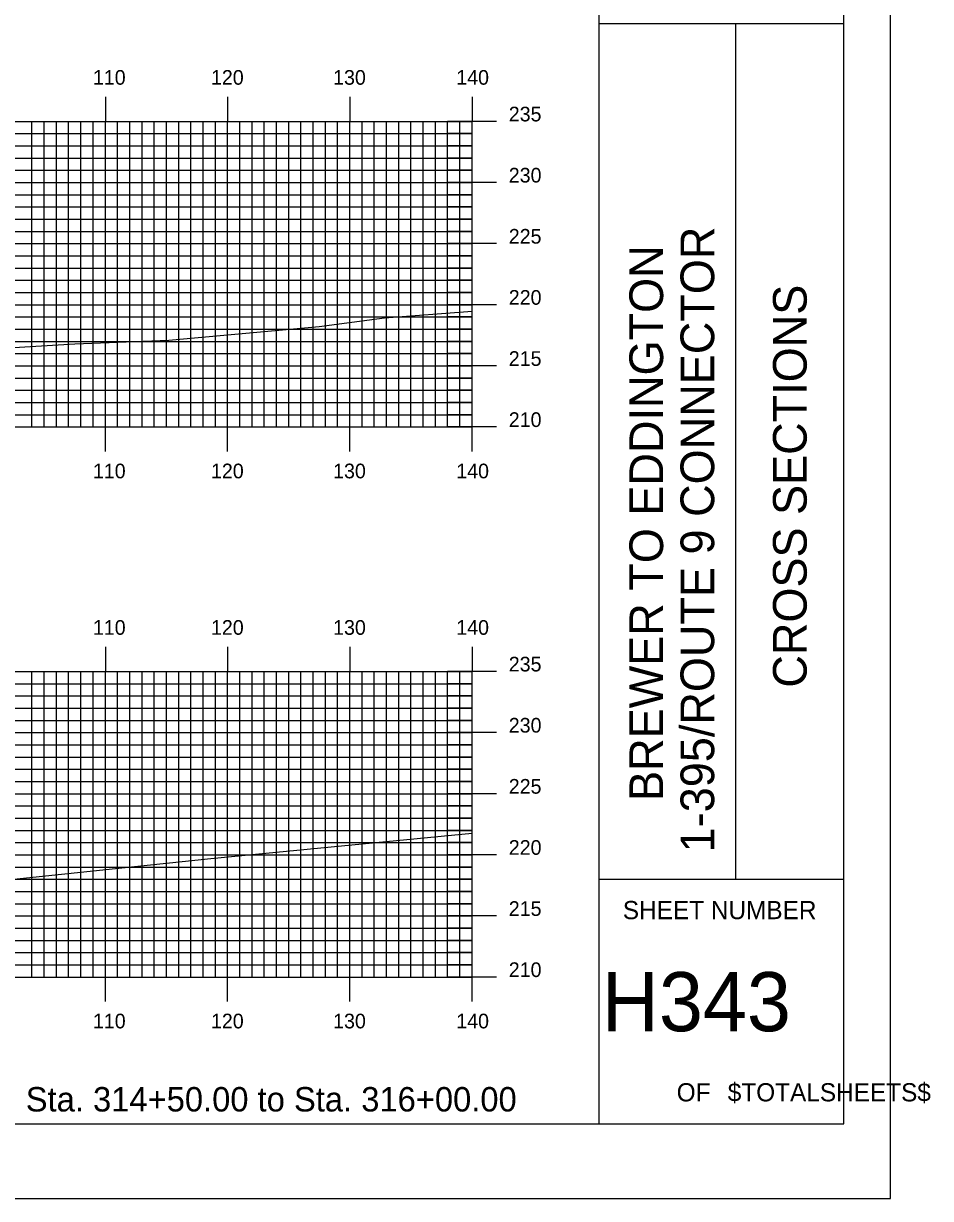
# Model space of a CAD drawing. Extents: x 1819244 to 1819587, y 442591 to 442811.
# Drawn here: x 1819513 to 1819587.2, y 442590.5 to 442686.7 of the extents above; entities that cross this region are included whole.
import ezdxf

# ---------------------------------------------------------------- set-up
doc = ezdxf.new("R2010")
doc.units = 0
for name, color, linetype in [('BORDER', 7, 'Continuous'), ('H_V ANNOTATION', 7, 'Continuous'), ('MAJOR', 7, 'Continuous'), ('MINOR', 7, 'Continuous'), ('PLOT BOUNDARY', 7, 'Continuous'), ('S_Roadway_Centerline', 7, 'Continuous')]:
    doc.layers.add(name, color=color, linetype=linetype)

msp = doc.modelspace()

# ---------------------------------------------------------------- linework, layer by layer
at = {"layer": 'BORDER'}
for p, q in [((1819560.065, 442596.665), (1819560.065, 442806.665)), ((1819560.065, 442686.671), (1819580.065, 442686.671)), ((1819571.247, 442616.671), (1819571.247, 442686.671)), ((1819560.065, 442616.671), (1819580.065, 442616.671))]:
    msp.add_line(p, q, dxfattribs=at)
msp.add_lwpolyline([(1819260.065, 442596.665), (1819580.065, 442596.665), (1819580.065, 442806.665), (1819260.065, 442806.665)], close=True, dxfattribs=at)
at = {"layer": 'MAJOR'}
for p, q in [((1819519.665, 442680.669), (1819519.665, 442678.665)), ((1819529.665, 442680.669), (1819529.665, 442678.665)), ((1819539.665, 442680.669), (1819539.665, 442678.665)), ((1819549.665, 442680.669), (1819549.665, 442678.665)), ((1819269.665, 442678.665), (1819549.665, 442678.665)), ((1819269.665, 442678.665), (1819549.665, 442678.665)), ((1819519.665, 442653.665), (1819519.665, 442678.665)), ((1819529.665, 442653.665), (1819529.665, 442678.665)), ((1819539.665, 442653.665), (1819539.665, 442678.665)), ((1819551.669, 442678.665), (1819547.661, 442678.665)), ((1819549.665, 442653.665), (1819549.665, 442678.665)), ((1819549.665, 442653.665), (1819549.665, 442678.665)), ((1819269.665, 442673.665), (1819549.665, 442673.665)), ((1819551.669, 442673.665), (1819547.661, 442673.665)), ((1819269.665, 442668.665), (1819549.665, 442668.665)), ((1819551.669, 442668.665), (1819547.661, 442668.665)), ((1819269.665, 442663.665), (1819549.665, 442663.665)), ((1819551.669, 442663.665), (1819547.661, 442663.665)), ((1819269.665, 442658.665), (1819549.665, 442658.665)), ((1819551.669, 442658.665), (1819547.661, 442658.665)), ((1819269.665, 442653.665), (1819549.665, 442653.665)), ((1819269.665, 442653.665), (1819549.665, 442653.665)), ((1819519.665, 442651.661), (1819519.665, 442653.665)), ((1819529.665, 442651.661), (1819529.665, 442653.665)), ((1819539.665, 442651.661), (1819539.665, 442653.665)), ((1819551.669, 442653.665), (1819547.661, 442653.665)), ((1819549.665, 442651.661), (1819549.665, 442653.665)), ((1819519.665, 442635.669), (1819519.665, 442633.665)), ((1819529.665, 442635.669), (1819529.665, 442633.665)), ((1819539.665, 442635.669), (1819539.665, 442633.665)), ((1819549.665, 442635.669), (1819549.665, 442633.665)), ((1819269.665, 442633.665), (1819549.665, 442633.665)), ((1819269.665, 442633.665), (1819549.665, 442633.665)), ((1819519.665, 442608.665), (1819519.665, 442633.665)), ((1819529.665, 442608.665), (1819529.665, 442633.665)), ((1819539.665, 442608.665), (1819539.665, 442633.665)), ((1819551.669, 442633.665), (1819547.661, 442633.665)), ((1819549.665, 442608.665), (1819549.665, 442633.665)), ((1819549.665, 442608.665), (1819549.665, 442633.665)), ((1819269.665, 442628.665), (1819549.665, 442628.665)), ((1819551.669, 442628.665), (1819547.661, 442628.665)), ((1819269.665, 442623.665), (1819549.665, 442623.665)), ((1819551.669, 442623.665), (1819547.661, 442623.665)), ((1819269.665, 442618.665), (1819549.665, 442618.665)), ((1819551.669, 442618.665), (1819547.661, 442618.665)), ((1819269.665, 442613.665), (1819549.665, 442613.665)), ((1819551.669, 442613.665), (1819547.661, 442613.665)), ((1819269.665, 442608.665), (1819549.665, 442608.665)), ((1819269.665, 442608.665), (1819549.665, 442608.665)), ((1819519.665, 442606.661), (1819519.665, 442608.665)), ((1819529.665, 442606.661), (1819529.665, 442608.665)), ((1819539.665, 442606.661), (1819539.665, 442608.665)), ((1819551.669, 442608.665), (1819547.661, 442608.665)), ((1819549.665, 442606.661), (1819549.665, 442608.665))]:
    msp.add_line(p, q, dxfattribs=at)
at = {"layer": 'MINOR'}
for p, q in [((1819513.665, 442653.665), (1819513.665, 442678.665)), ((1819514.665, 442653.665), (1819514.665, 442678.665)), ((1819515.665, 442653.665), (1819515.665, 442678.665)), ((1819516.665, 442653.665), (1819516.665, 442678.665)), ((1819517.665, 442653.665), (1819517.665, 442678.665)), ((1819518.665, 442653.665), (1819518.665, 442678.665)), ((1819520.665, 442653.665), (1819520.665, 442678.665)), ((1819521.665, 442653.665), (1819521.665, 442678.665)), ((1819522.665, 442653.665), (1819522.665, 442678.665)), ((1819523.665, 442653.665), (1819523.665, 442678.665)), ((1819524.665, 442653.665), (1819524.665, 442678.665)), ((1819525.665, 442653.665), (1819525.665, 442678.665)), ((1819526.665, 442653.665), (1819526.665, 442678.665)), ((1819527.665, 442653.665), (1819527.665, 442678.665)), ((1819528.665, 442653.665), (1819528.665, 442678.665)), ((1819530.665, 442653.665), (1819530.665, 442678.665)), ((1819531.665, 442653.665), (1819531.665, 442678.665)), ((1819532.665, 442653.665), (1819532.665, 442678.665)), ((1819533.665, 442653.665), (1819533.665, 442678.665)), ((1819534.665, 442653.665), (1819534.665, 442678.665)), ((1819535.665, 442653.665), (1819535.665, 442678.665)), ((1819536.665, 442653.665), (1819536.665, 442678.665)), ((1819537.665, 442653.665), (1819537.665, 442678.665)), ((1819538.665, 442653.665), (1819538.665, 442678.665)), ((1819540.665, 442653.665), (1819540.665, 442678.665)), ((1819541.665, 442653.665), (1819541.665, 442678.665)), ((1819542.665, 442653.665), (1819542.665, 442678.665)), ((1819543.665, 442653.665), (1819543.665, 442678.665)), ((1819544.665, 442653.665), (1819544.665, 442678.665)), ((1819545.665, 442653.665), (1819545.665, 442678.665)), ((1819546.665, 442653.665), (1819546.665, 442678.665)), ((1819547.665, 442653.665), (1819547.665, 442678.665)), ((1819548.665, 442653.665), (1819548.665, 442678.665)), ((1819269.665, 442677.665), (1819549.665, 442677.665)), ((1819549.665, 442677.665), (1819547.661, 442677.665)), ((1819269.665, 442676.665), (1819549.665, 442676.665)), ((1819549.665, 442676.665), (1819547.661, 442676.665)), ((1819269.665, 442675.665), (1819549.665, 442675.665)), ((1819549.665, 442675.665), (1819547.661, 442675.665)), ((1819269.665, 442674.665), (1819549.665, 442674.665)), ((1819549.665, 442674.665), (1819547.661, 442674.665)), ((1819269.665, 442672.665), (1819549.665, 442672.665)), ((1819549.665, 442672.665), (1819547.661, 442672.665)), ((1819269.665, 442671.665), (1819549.665, 442671.665)), ((1819549.665, 442671.665), (1819547.661, 442671.665)), ((1819269.665, 442670.665), (1819549.665, 442670.665)), ((1819549.665, 442670.665), (1819547.661, 442670.665)), ((1819269.665, 442669.665), (1819549.665, 442669.665)), ((1819549.665, 442669.665), (1819547.661, 442669.665)), ((1819269.665, 442667.665), (1819549.665, 442667.665)), ((1819549.665, 442667.665), (1819547.661, 442667.665)), ((1819269.665, 442666.665), (1819549.665, 442666.665)), ((1819549.665, 442666.665), (1819547.661, 442666.665)), ((1819269.665, 442665.665), (1819549.665, 442665.665)), ((1819549.665, 442665.665), (1819547.661, 442665.665)), ((1819269.665, 442664.665), (1819549.665, 442664.665)), ((1819549.665, 442664.665), (1819547.661, 442664.665)), ((1819269.665, 442662.665), (1819549.665, 442662.665)), ((1819549.665, 442662.665), (1819547.661, 442662.665)), ((1819269.665, 442661.665), (1819549.665, 442661.665)), ((1819549.665, 442661.665), (1819547.661, 442661.665)), ((1819269.665, 442660.665), (1819549.665, 442660.665)), ((1819549.665, 442660.665), (1819547.661, 442660.665)), ((1819269.665, 442659.665), (1819549.665, 442659.665)), ((1819549.665, 442659.665), (1819547.661, 442659.665)), ((1819269.665, 442657.665), (1819549.665, 442657.665)), ((1819549.665, 442657.665), (1819547.661, 442657.665)), ((1819269.665, 442656.665), (1819549.665, 442656.665)), ((1819549.665, 442656.665), (1819547.661, 442656.665)), ((1819269.665, 442655.665), (1819549.665, 442655.665)), ((1819549.665, 442655.665), (1819547.661, 442655.665)), ((1819269.665, 442654.665), (1819549.665, 442654.665)), ((1819549.665, 442654.665), (1819547.661, 442654.665)), ((1819513.665, 442608.665), (1819513.665, 442633.665)), ((1819514.665, 442608.665), (1819514.665, 442633.665)), ((1819515.665, 442608.665), (1819515.665, 442633.665)), ((1819516.665, 442608.665), (1819516.665, 442633.665)), ((1819517.665, 442608.665), (1819517.665, 442633.665)), ((1819518.665, 442608.665), (1819518.665, 442633.665)), ((1819520.665, 442608.665), (1819520.665, 442633.665)), ((1819521.665, 442608.665), (1819521.665, 442633.665)), ((1819522.665, 442608.665), (1819522.665, 442633.665)), ((1819523.665, 442608.665), (1819523.665, 442633.665)), ((1819524.665, 442608.665), (1819524.665, 442633.665)), ((1819525.665, 442608.665), (1819525.665, 442633.665)), ((1819526.665, 442608.665), (1819526.665, 442633.665)), ((1819527.665, 442608.665), (1819527.665, 442633.665)), ((1819528.665, 442608.665), (1819528.665, 442633.665)), ((1819530.665, 442608.665), (1819530.665, 442633.665)), ((1819531.665, 442608.665), (1819531.665, 442633.665)), ((1819532.665, 442608.665), (1819532.665, 442633.665)), ((1819533.665, 442608.665), (1819533.665, 442633.665)), ((1819534.665, 442608.665), (1819534.665, 442633.665)), ((1819535.665, 442608.665), (1819535.665, 442633.665)), ((1819536.665, 442608.665), (1819536.665, 442633.665)), ((1819537.665, 442608.665), (1819537.665, 442633.665)), ((1819538.665, 442608.665), (1819538.665, 442633.665)), ((1819540.665, 442608.665), (1819540.665, 442633.665)), ((1819541.665, 442608.665), (1819541.665, 442633.665)), ((1819542.665, 442608.665), (1819542.665, 442633.665)), ((1819543.665, 442608.665), (1819543.665, 442633.665)), ((1819544.665, 442608.665), (1819544.665, 442633.665)), ((1819545.665, 442608.665), (1819545.665, 442633.665)), ((1819546.665, 442608.665), (1819546.665, 442633.665)), ((1819547.665, 442608.665), (1819547.665, 442633.665)), ((1819548.665, 442608.665), (1819548.665, 442633.665)), ((1819269.665, 442632.665), (1819549.665, 442632.665)), ((1819549.665, 442632.665), (1819547.661, 442632.665)), ((1819269.665, 442631.665), (1819549.665, 442631.665)), ((1819549.665, 442631.665), (1819547.661, 442631.665)), ((1819269.665, 442630.665), (1819549.665, 442630.665)), ((1819549.665, 442630.665), (1819547.661, 442630.665)), ((1819269.665, 442629.665), (1819549.665, 442629.665)), ((1819549.665, 442629.665), (1819547.661, 442629.665)), ((1819269.665, 442627.665), (1819549.665, 442627.665)), ((1819549.665, 442627.665), (1819547.661, 442627.665)), ((1819269.665, 442626.665), (1819549.665, 442626.665)), ((1819549.665, 442626.665), (1819547.661, 442626.665)), ((1819269.665, 442625.665), (1819549.665, 442625.665)), ((1819549.665, 442625.665), (1819547.661, 442625.665)), ((1819269.665, 442624.665), (1819549.665, 442624.665)), ((1819549.665, 442624.665), (1819547.661, 442624.665)), ((1819269.665, 442622.665), (1819549.665, 442622.665)), ((1819549.665, 442622.665), (1819547.661, 442622.665)), ((1819269.665, 442621.665), (1819549.665, 442621.665)), ((1819549.665, 442621.665), (1819547.661, 442621.665)), ((1819269.665, 442620.665), (1819549.665, 442620.665)), ((1819549.665, 442620.665), (1819547.661, 442620.665)), ((1819269.665, 442619.665), (1819549.665, 442619.665)), ((1819549.665, 442619.665), (1819547.661, 442619.665)), ((1819269.665, 442617.665), (1819549.665, 442617.665)), ((1819549.665, 442617.665), (1819547.661, 442617.665)), ((1819269.665, 442616.665), (1819549.665, 442616.665)), ((1819549.665, 442616.665), (1819547.661, 442616.665)), ((1819269.665, 442615.665), (1819549.665, 442615.665)), ((1819549.665, 442615.665), (1819547.661, 442615.665)), ((1819269.665, 442614.665), (1819549.665, 442614.665)), ((1819549.665, 442614.665), (1819547.661, 442614.665)), ((1819269.665, 442612.665), (1819549.665, 442612.665)), ((1819549.665, 442612.665), (1819547.661, 442612.665)), ((1819269.665, 442611.665), (1819549.665, 442611.665)), ((1819549.665, 442611.665), (1819547.661, 442611.665)), ((1819269.665, 442610.665), (1819549.665, 442610.665)), ((1819549.665, 442610.665), (1819547.661, 442610.665)), ((1819269.665, 442609.665), (1819549.665, 442609.665)), ((1819549.665, 442609.665), (1819547.661, 442609.665))]:
    msp.add_line(p, q, dxfattribs=at)
at = {"layer": 'PLOT BOUNDARY'}
msp.add_lwpolyline([(1819243.878, 442590.547), (1819583.878, 442590.547), (1819583.878, 442810.547), (1819243.878, 442810.547)], close=True, dxfattribs=at)
at = {"layer": 'S_Roadway_Centerline'}
for points in [[(1819453.663, 442659.344), (1819475.455, 442659.085), (1819482.736, 442659.152), (1819497.564, 442659.463), (1819509.416, 442660.014), (1819517.174, 442660.466), (1819524.87, 442660.759), (1819537.148, 442661.896), (1819542.486, 442662.603), (1819549.665, 442663.134)], [(1819469.488, 442614.315), (1819471.654, 442614.398), (1819473.184, 442614.498), (1819487.884, 442614.82), (1819508.262, 442616.254), (1819528.3, 442618.36), (1819549.665, 442620.426)]]:
    msp.add_lwpolyline(points, dxfattribs=at)

# ---------------------------------------------------------------- texts
at = {"layer": 'BORDER'}
for s, p in [('1-395/ROUTE 9 CONNECTOR', (1819569.468, 442618.865)), ('BREWER TO EDDINGTON', (1819565.289, 442623.074)), ('CROSS SECTIONS', (1819577.034, 442632.339))]:
    msp.add_text(s, height=2.75575, rotation=90, dxfattribs=at).set_placement(p)
for s, height, p in [('SHEET NUMBER', 1.49054, (1819561.996, 442613.398)), ('H343', 4.8388, (1819560.275, 442604.23)), ('OF', 1.4905, (1819566.399, 442598.491)), ('$TOTALSHEETS$', 1.49054, (1819570.578, 442598.491))]:
    msp.add_text(s, height=height, dxfattribs=at).set_placement(p)
at = {"layer": 'H_V ANNOTATION'}
for s, height, p in [('110', 1.2, (1819518.648, 442681.665)), ('120', 1.2, (1819528.305, 442681.665)), ('130', 1.2, (1819538.295, 442681.665)), ('140', 1.2, (1819548.369, 442681.665)), ('235', 1.2, (1819552.665, 442678.665)), ('230', 1.2, (1819552.665, 442673.665)), ('225', 1.2, (1819552.665, 442668.665)), ('220', 1.2, (1819552.665, 442663.665)), ('215', 1.2, (1819552.665, 442658.665)), ('210', 1.2, (1819552.665, 442653.665)), ('110', 1.2, (1819518.648, 442649.465)), ('120', 1.2, (1819528.305, 442649.465)), ('130', 1.2, (1819538.295, 442649.465)), ('140', 1.2, (1819548.369, 442649.465)), ('110', 1.2, (1819518.648, 442636.665)), ('120', 1.2, (1819528.305, 442636.665)), ('130', 1.2, (1819538.295, 442636.665)), ('140', 1.2, (1819548.369, 442636.665)), ('235', 1.2, (1819552.665, 442633.665)), ('230', 1.2, (1819552.665, 442628.665)), ('225', 1.2, (1819552.665, 442623.665)), ('220', 1.2, (1819552.665, 442618.665)), ('215', 1.2, (1819552.665, 442613.665)), ('210', 1.2, (1819552.665, 442608.665)), ('110', 1.2, (1819518.648, 442604.465)), ('120', 1.2, (1819528.305, 442604.465)), ('130', 1.2, (1819538.295, 442604.465)), ('140', 1.2, (1819548.369, 442604.465)), ('Sta. 314+50.00 to Sta. 316+00.00', 2.0004, (1819513.156, 442597.665))]:
    msp.add_text(s, height=height, dxfattribs=at).set_placement(p)

doc.saveas('drawing.dxf')
